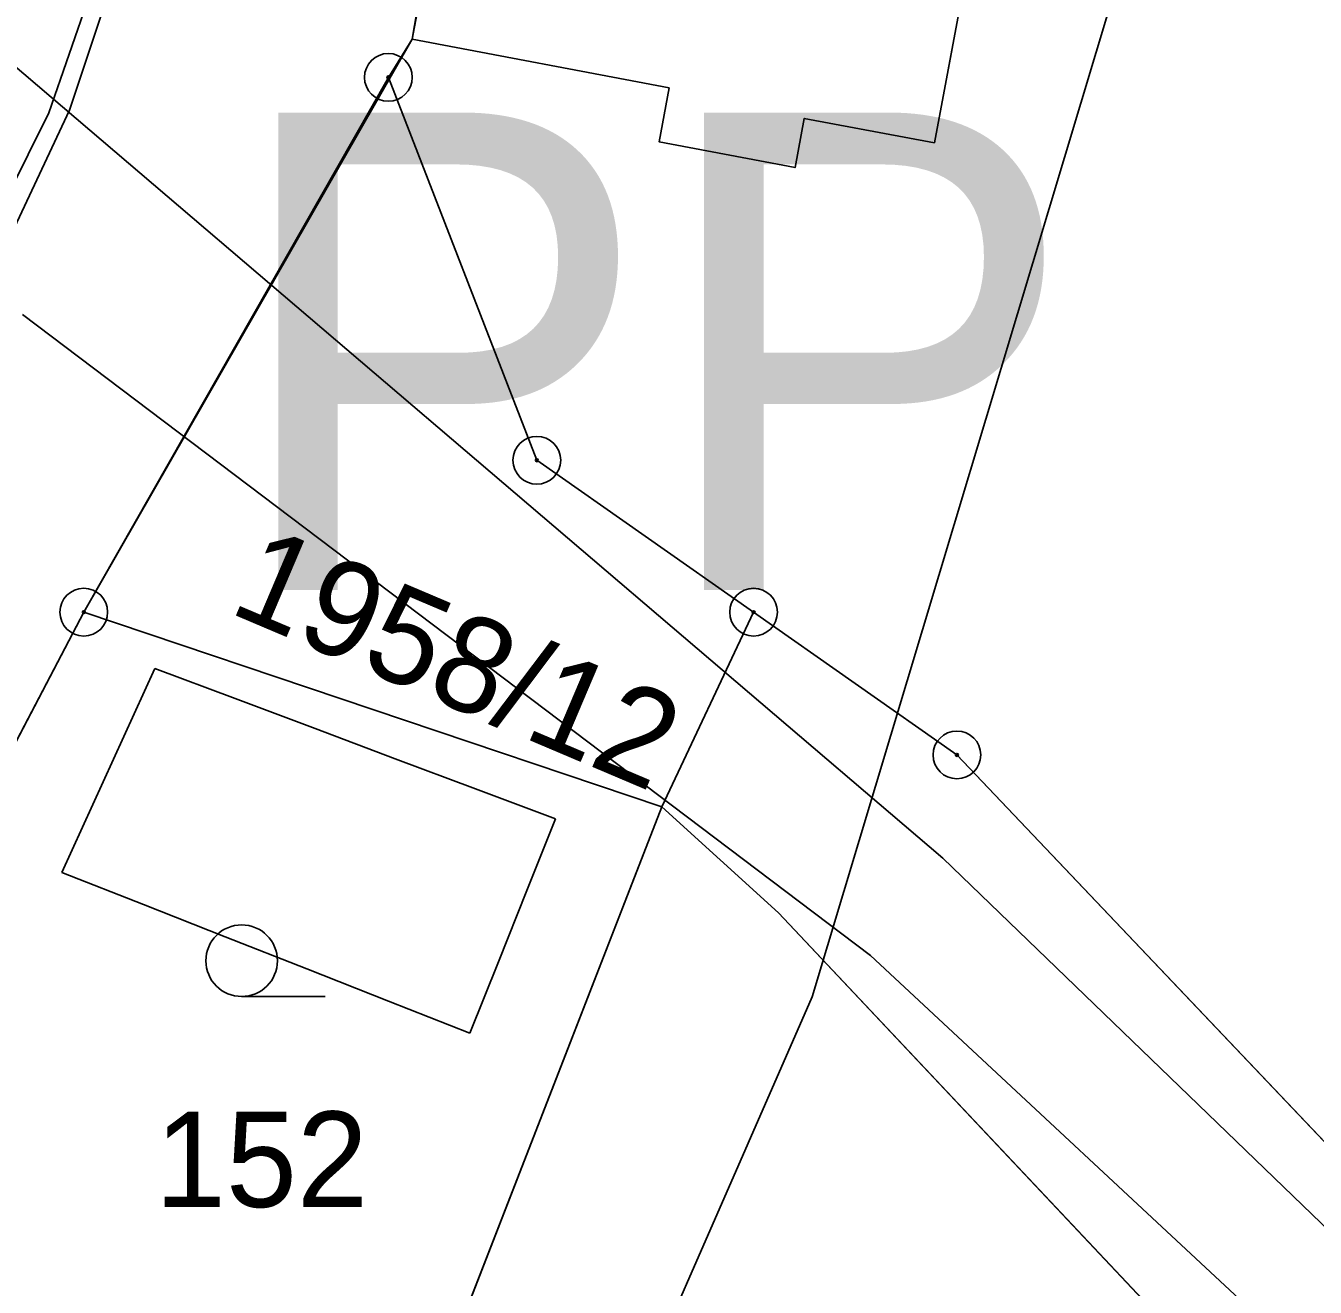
# Model space of a CAD drawing. Extents: x -706130 to -698555, y -971544 to -967260.
# Drawn here: x -704338.67 to -704311.66, y -970237.74 to -970211.32 of the extents above; entities that cross this region are included whole.
import ezdxf

# ---------------------------------------------------------------- set-up
doc = ezdxf.new("R2010")
doc.units = 0
for name, color, linetype in [('_Doplněk budov pro zastavěnost', 7, 'Continuous'), ('BPEJ I-II trida ochrany S', 7, 'Continuous'), ('Docházková izochrona - BUS S', 7, 'Continuous'), ('Docházková izochrona - VLAK N', 7, 'Continuous'), ('Hranice intravilán', 7, 'Continuous'), ('Kanalizace_stoka bez rozlišení N', 7, 'Continuous'), ('KN_Budovy', 7, 'Continuous'), ('KN_Hranice_parcel', 7, 'Continuous'), ('KN_Hranice_parcel_vnitrni_kresba', 7, 'Continuous'), ('KN_Parcelni cisla', 7, 'Continuous'), ('KN_Polygon parcely', 7, 'Continuous'), ('KN_POZEMKY_13_ZASTAVENA PLOCHA', 7, 'Continuous'), ('KN_POZEMKY_14_OSTATNI PLOCHA', 7, 'Continuous'), ('KN_POZEMKY_5_ZAHRADA', 7, 'Continuous'), ('KN_POZEMKY_7_TTP', 7, 'Continuous'), ('KN_VYUZITI_16_ostatni plocha_silnice', 7, 'Continuous'), ('KN_VYUZITI_17_ostatni plocha_ostatni komunikace', 7, 'Continuous'), ('KN_Značky bodu BP', 7, 'Continuous'), ('KN_Značky kultur', 7, 'Continuous'), ('Komunikace III třídy osy S', 7, 'Continuous'), ('Plochy doprava silniční - silnice III třídy S', 7, 'Continuous'), ('Plochy N_P ŠRAFY', 7, 'Continuous'), ('Plochy smíšené obytné venkovské N', 7, 'Continuous'), ('Plochy smíšené obytné venkovské S', 7, 'Continuous'), ('Plochy verejnych prostranstvi - komunikace ostatni S', 7, 'Continuous'), ('Plochy vodní a vodních toku_linie zatrubněný tok S', 7, 'Continuous'), ('Plochy zmen_ zastavitelne plochy', 7, 'Continuous'), ('Plochy zmen_ zastavitelne plochy_ZAKL', 7, 'Continuous'), ('Plynovody STL N', 7, 'Continuous'), ('Regulační bloky zastavitelné N', 7, 'Continuous'), ('Regulační bloky zastavěné S', 7, 'Continuous'), ('Regulační kódy zastavěné S', 7, 'Continuous'), ('Trasy cykloturistické N', 7, 'Continuous'), ('Zastavene uzemi N', 7, 'Continuous'), ('Zastavene uzemi plochy N', 7, 'Continuous'), ('Zábory hodnocené - plochy', 7, 'Continuous'), ('Zábory hodnocené - prevzate z UPO I a II tridy ochrany ZPF', 7, 'Continuous')]:
    doc.layers.add(name, color=color, linetype=linetype)

msp = doc.modelspace()

# ---------------------------------------------------------------- linework, layer by layer
at = {"layer": '_Doplněk budov pro zastavěnost'}
for p, q in [((-704336.61, -970226.203), (-704335.96, -970224.78)), ((-704335.96, -970224.78), (-704334.282, -970225.41)), ((-704334.282, -970225.41), (-704332.604, -970226.04)), ((-704332.604, -970226.04), (-704330.926, -970226.67)), ((-704337.26, -970227.627), (-704336.61, -970226.203)), ((-704330.926, -970226.67), (-704329.248, -970227.3)), ((-704329.248, -970227.3), (-704327.57, -970227.93)), ((-704337.91, -970229.05), (-704337.26, -970227.627)), ((-704327.57, -970227.93), (-704328.167, -970229.427)), ((-704336.2, -970229.724), (-704337.91, -970229.05)), ((-704328.167, -970229.427), (-704328.763, -970230.923)), ((-704334.49, -970230.398), (-704336.2, -970229.724)), ((-704332.78, -970231.072), (-704334.49, -970230.398)), ((-704328.763, -970230.923), (-704329.36, -970232.42)), ((-704331.07, -970231.746), (-704332.78, -970231.072)), ((-704329.36, -970232.42), (-704331.07, -970231.746))]:
    msp.add_line(p, q, dxfattribs=at)
at = {"layer": 'BPEJ I-II trida ochrany S'}
for p, q in [((-704337.45, -970223.6), (-704350.46, -970248.43)), ((-704325.34, -970227.68), (-704337.45, -970223.6)), ((-704322.9, -970229.9), (-704325.34, -970227.68)), ((-704300.46, -970253.7), (-704322.9, -970229.9))]:
    msp.add_line(p, q, dxfattribs=at)
at = {"layer": 'Docházková izochrona - BUS S'}
msp.add_arc((-704361.829, -969946.93), 400, 155.51821, 17.33949, dxfattribs=at)
at = {"layer": 'Docházková izochrona - VLAK N'}
msp.add_circle((-704165.451, -969778.767), 800, dxfattribs=at)
at = {"layer": 'Hranice intravilán'}
msp.add_lwpolyline([(-704236.96, -970276.21), (-704246.98, -970274.18), (-704251.4, -970273.29), (-704285.92, -970266.3), (-704300.46, -970253.7), (-704322.9, -970229.9), (-704325.34, -970227.68), (-704336.11, -970255.37), (-704346.87, -970276.54), (-704326.71, -970292.84)], dxfattribs=at)
at = {"layer": 'Kanalizace_stoka bez rozlišení N'}
for points in [[(-704315.708, -970108.899), (-704316.113, -970109.917), (-704324.867, -970134.026), (-704326.632, -970179.784), (-704337.75, -970213.085), (-704365.425, -970272.107), (-704371.374, -970294.506), (-704373.709, -970351.804), (-704376.113, -970385.719), (-704398.194, -970423.758)], [(-704338.733, -970217.369), (-704320.973, -970230.788), (-704296.056, -970253.992)]]:
    msp.add_lwpolyline(points, dxfattribs=at)
at = {"layer": 'KN_Budovy'}
msp.add_lwpolyline([(-704330.57, -970211.6), (-704325.19, -970212.62), (-704325.4, -970213.75), (-704322.55, -970214.29), (-704322.36, -970213.26), (-704319.63, -970213.77), (-704317.74, -970203.66), (-704328.65, -970201.47)], close=True, dxfattribs=at)
at = {"layer": 'KN_Hranice_parcel'}
for p, q in [((-704331.07, -970212.4), (-704337.45, -970223.6)), ((-704337.45, -970223.6), (-704350.46, -970248.43)), ((-704325.34, -970227.68), (-704337.45, -970223.6)), ((-704325.34, -970227.68), (-704323.42, -970223.6)), ((-704336.11, -970255.37), (-704325.34, -970227.68))]:
    msp.add_line(p, q, dxfattribs=at)
for points in [[(-704328.2, -970197.68), (-704328.65, -970201.47), (-704330.57, -970211.6), (-704331.07, -970212.4)], [(-704331.07, -970212.4), (-704327.96, -970220.42), (-704323.42, -970223.6)], [(-704323.42, -970223.6), (-704319.16, -970226.59), (-704310.29, -970235.93)], [(-704285.92, -970266.3), (-704300.46, -970253.7), (-704322.9, -970229.9), (-704325.34, -970227.68)]]:
    msp.add_lwpolyline(points, dxfattribs=at)
at = {"layer": 'KN_Hranice_parcel_vnitrni_kresba'}
for p, q in [((-704317.74, -970203.66), (-704319.63, -970213.77)), ((-704325.19, -970212.62), (-704330.57, -970211.6)), ((-704325.4, -970213.75), (-704325.19, -970212.62)), ((-704322.36, -970213.26), (-704322.55, -970214.29)), ((-704322.36, -970213.26), (-704319.63, -970213.77)), ((-704322.55, -970214.29), (-704325.4, -970213.75))]:
    msp.add_line(p, q, dxfattribs=at)
at = {"layer": 'KN_Polygon parcely'}
msp.add_lwpolyline([(-704366.65, -970284.79), (-704361.08, -970269.38), (-704350.46, -970248.43), (-704337.45, -970223.6), (-704331.07, -970212.4), (-704330.57, -970211.6), (-704328.65, -970201.47), (-704328.2, -970197.68), (-704327.21, -970194.48), (-704325.58, -970189.23)], dxfattribs=at)
for points in [[(-704330.57, -970211.6), (-704331.07, -970212.4), (-704327.96, -970220.42), (-704323.42, -970223.6), (-704319.16, -970226.59), (-704310.29, -970235.93), (-704306.81, -970220.57), (-704303.37, -970205.4), (-704328.2, -970197.68), (-704328.65, -970201.47)], [(-704325.34, -970227.68), (-704323.42, -970223.6), (-704327.96, -970220.42), (-704331.07, -970212.4), (-704337.45, -970223.6)], [(-704348.38, -970249.44), (-704336.11, -970255.37), (-704325.34, -970227.68), (-704337.45, -970223.6), (-704350.46, -970248.43)], [(-704244.89, -970266.42), (-704259.77, -970263.46), (-704260.88, -970266.75), (-704271.05, -970261.53), (-704272.58, -970261.48), (-704284.35, -970261.07), (-704290.77, -970255.89), (-704294.48, -970248.59), (-704302.85, -970243.53), (-704310.29, -970235.93), (-704319.16, -970226.59), (-704323.42, -970223.6), (-704325.34, -970227.68), (-704322.9, -970229.9), (-704300.46, -970253.7), (-704285.92, -970266.3), (-704251.4, -970273.29), (-704246.98, -970274.18)], [(-704266.41, -970278.02), (-704277.06, -970272.43), (-704285.92, -970266.3), (-704300.46, -970253.7), (-704322.9, -970229.9), (-704325.34, -970227.68), (-704336.11, -970255.37), (-704346.87, -970276.54), (-704326.71, -970292.84), (-704284.63, -970309.07), (-704263.93, -970315.92)]]:
    msp.add_lwpolyline(points, close=True, dxfattribs=at)
at = {"layer": 'KN_POZEMKY_13_ZASTAVENA PLOCHA'}
for p, q in [((-704330.57, -970211.6), (-704328.65, -970201.47)), ((-704331.07, -970212.4), (-704330.57, -970211.6)), ((-704327.96, -970220.42), (-704331.07, -970212.4)), ((-704323.42, -970223.6), (-704327.96, -970220.42)), ((-704319.16, -970226.59), (-704323.42, -970223.6)), ((-704310.29, -970235.93), (-704319.16, -970226.59))]:
    msp.add_line(p, q, dxfattribs=at)
at = {"layer": 'KN_POZEMKY_14_OSTATNI PLOCHA'}
for p, q in [((-704328.65, -970201.47), (-704330.57, -970211.6)), ((-704330.57, -970211.6), (-704331.07, -970212.4)), ((-704331.07, -970212.4), (-704337.45, -970223.6)), ((-704337.45, -970223.6), (-704331.07, -970212.4)), ((-704331.07, -970212.4), (-704327.96, -970220.42)), ((-704327.96, -970220.42), (-704323.42, -970223.6)), ((-704337.45, -970223.6), (-704350.46, -970248.43)), ((-704325.34, -970227.68), (-704337.45, -970223.6)), ((-704325.34, -970227.68), (-704323.42, -970223.6)), ((-704323.42, -970223.6), (-704325.34, -970227.68)), ((-704323.42, -970223.6), (-704319.16, -970226.59)), ((-704319.16, -970226.59), (-704310.29, -970235.93)), ((-704322.9, -970229.9), (-704325.34, -970227.68)), ((-704300.46, -970253.7), (-704322.9, -970229.9))]:
    msp.add_line(p, q, dxfattribs=at)
at = {"layer": 'KN_POZEMKY_5_ZAHRADA'}
for p, q in [((-704350.46, -970248.43), (-704337.45, -970223.6)), ((-704337.45, -970223.6), (-704325.34, -970227.68)), ((-704325.34, -970227.68), (-704336.11, -970255.37))]:
    msp.add_line(p, q, dxfattribs=at)
at = {"layer": 'KN_POZEMKY_7_TTP'}
for p, q in [((-704336.11, -970255.37), (-704325.34, -970227.68)), ((-704325.34, -970227.68), (-704322.9, -970229.9)), ((-704322.9, -970229.9), (-704300.46, -970253.7))]:
    msp.add_line(p, q, dxfattribs=at)
at = {"layer": 'KN_VYUZITI_16_ostatni plocha_silnice'}
for p, q in [((-704328.65, -970201.47), (-704330.57, -970211.6)), ((-704330.57, -970211.6), (-704331.07, -970212.4)), ((-704331.07, -970212.4), (-704337.45, -970223.6)), ((-704337.45, -970223.6), (-704350.46, -970248.43))]:
    msp.add_line(p, q, dxfattribs=at)
at = {"layer": 'KN_VYUZITI_17_ostatni plocha_ostatni komunikace'}
for p, q in [((-704337.45, -970223.6), (-704331.07, -970212.4)), ((-704331.07, -970212.4), (-704327.96, -970220.42)), ((-704327.96, -970220.42), (-704323.42, -970223.6)), ((-704325.34, -970227.68), (-704337.45, -970223.6)), ((-704325.34, -970227.68), (-704323.42, -970223.6)), ((-704323.42, -970223.6), (-704325.34, -970227.68)), ((-704323.42, -970223.6), (-704319.16, -970226.59)), ((-704319.16, -970226.59), (-704310.29, -970235.93)), ((-704322.9, -970229.9), (-704325.34, -970227.68)), ((-704300.46, -970253.7), (-704322.9, -970229.9))]:
    msp.add_line(p, q, dxfattribs=at)
at = {"layer": 'KN_Značky bodu BP'}
for centre, radius in [((-704331.07, -970212.4), 0.5), ((-704331.07, -970212.4), 0.0303), ((-704327.96, -970220.42), 0.5), ((-704327.96, -970220.42), 0.0303), ((-704337.45, -970223.6), 0.5), ((-704323.42, -970223.6), 0.5), ((-704337.45, -970223.6), 0.0303), ((-704323.42, -970223.6), 0.0303), ((-704319.16, -970226.59), 0.5), ((-704319.16, -970226.59), 0.0303)]:
    msp.add_circle(centre, radius, dxfattribs=at)
at = {"layer": 'KN_Značky kultur'}
msp.add_line((-704334.143, -970231.65), (-704332.393, -970231.65), dxfattribs=at)
msp.add_circle((-704334.143, -970230.9), 0.75, dxfattribs=at)
at = {"layer": 'Komunikace III třídy osy S'}
msp.add_lwpolyline([(-704330.93, -970188.51), (-704335.437, -970204.681), (-704336.48, -970208.22), (-704338.18, -970213.14), (-704340.791, -970218.395), (-704362.238, -970261.156), (-704368.668, -970276.027), (-704371.631, -970286.925), (-704374.154, -970304.881), (-704375.815, -970349.829), (-704377.52, -970379.09), (-704378.33, -970382.9), (-704379.81, -970387.16), (-704381.8, -970391.97), (-704383.72, -970396.25), (-704386.32, -970401.18), (-704392.36, -970410.73), (-704399.98, -970422.96)], dxfattribs=at)
at = {"layer": 'Plochy doprava silniční - silnice III třídy S'}
for p, q in [((-704330.57, -970211.6), (-704328.65, -970201.47)), ((-704331.07, -970212.4), (-704330.57, -970211.6)), ((-704337.45, -970223.6), (-704331.07, -970212.4)), ((-704350.46, -970248.43), (-704337.45, -970223.6))]:
    msp.add_line(p, q, dxfattribs=at)
at = {"layer": 'Plochy N_P ŠRAFY'}
for p, q in [((-704323.42, -970223.6), (-704325.34, -970227.68)), ((-704325.34, -970227.68), (-704336.11, -970255.37))]:
    msp.add_line(p, q, dxfattribs=at)
msp.add_lwpolyline([(-704310.29, -970235.93), (-704319.16, -970226.59), (-704323.42, -970223.6)], dxfattribs=at)
at = {"layer": 'Plochy smíšené obytné venkovské N'}
for p, q in [((-704323.42, -970223.6), (-704325.34, -970227.68)), ((-704325.34, -970227.68), (-704336.11, -970255.37))]:
    msp.add_line(p, q, dxfattribs=at)
msp.add_lwpolyline([(-704310.29, -970235.93), (-704319.16, -970226.59), (-704323.42, -970223.6)], dxfattribs=at)
at = {"layer": 'Plochy smíšené obytné venkovské S'}
for p, q in [((-704328.65, -970201.47), (-704330.57, -970211.6)), ((-704330.57, -970211.6), (-704331.07, -970212.4)), ((-704337.45, -970223.6), (-704350.46, -970248.43)), ((-704325.34, -970227.68), (-704337.45, -970223.6)), ((-704336.11, -970255.37), (-704325.34, -970227.68))]:
    msp.add_line(p, q, dxfattribs=at)
for points in [[(-704331.07, -970212.4), (-704327.96, -970220.42), (-704323.42, -970223.6)], [(-704323.42, -970223.6), (-704319.16, -970226.59), (-704310.29, -970235.93)]]:
    msp.add_lwpolyline(points, dxfattribs=at)
at = {"layer": 'Plochy verejnych prostranstvi - komunikace ostatni S'}
for p, q in [((-704331.07, -970212.4), (-704337.45, -970223.6)), ((-704327.96, -970220.42), (-704331.07, -970212.4)), ((-704323.42, -970223.6), (-704327.96, -970220.42)), ((-704337.45, -970223.6), (-704325.34, -970227.68)), ((-704325.34, -970227.68), (-704323.42, -970223.6))]:
    msp.add_line(p, q, dxfattribs=at)
at = {"layer": 'Plochy vodní a vodních toku_linie zatrubněný tok S'}
for points in [[(-704322.195, -970231.658), (-704315.577, -970209.662), (-704310.452, -970190.609), (-704310.025, -970177.978), (-704308.103, -970157.425), (-704307.462, -970138.586), (-704307.462, -970124.666), (-704314.585, -970112.421), (-704319.309, -970105.942)], [(-704351.63, -970286.842), (-704343.453, -970280.248), (-704322.195, -970231.658)]]:
    msp.add_lwpolyline(points, dxfattribs=at)
at = {"layer": 'Plochy zmen_ zastavitelne plochy'}
msp.add_lwpolyline([(-704351.62, -970285.42), (-704346.87, -970276.54), (-704336.11, -970255.37), (-704325.34, -970227.68), (-704323.42, -970223.6), (-704319.16, -970226.59), (-704310.29, -970235.93), (-704302.85, -970243.53), (-704294.48, -970248.59), (-704286.71, -970225.41), (-704281.8, -970209.65), (-704275.41, -970210.91), (-704251.29, -970214.31), (-704249.33, -970214.59), (-704249.17, -970213.48), (-704247.74, -970203.29), (-704230.21, -970196.19)], dxfattribs=at)
at = {"layer": 'Plochy zmen_ zastavitelne plochy_ZAKL'}
for p, q in [((-704323.42, -970223.6), (-704325.34, -970227.68)), ((-704325.34, -970227.68), (-704336.11, -970255.37))]:
    msp.add_line(p, q, dxfattribs=at)
msp.add_lwpolyline([(-704310.29, -970235.93), (-704319.16, -970226.59), (-704323.42, -970223.6)], dxfattribs=at)
at = {"layer": 'Plynovody STL N'}
msp.add_lwpolyline([(-704341.145, -970210.248), (-704319.452, -970228.75), (-704295.073, -970252.27)], dxfattribs=at)
at = {"layer": 'Regulační bloky zastavitelné N'}
for p, q in [((-704323.42, -970223.6), (-704325.34, -970227.68)), ((-704325.34, -970227.68), (-704336.11, -970255.37))]:
    msp.add_line(p, q, dxfattribs=at)
msp.add_lwpolyline([(-704310.29, -970235.93), (-704319.16, -970226.59), (-704323.42, -970223.6)], dxfattribs=at)
at = {"layer": 'Regulační bloky zastavěné S'}
for p, q in [((-704330.57, -970211.6), (-704328.65, -970201.47)), ((-704328.65, -970201.47), (-704330.57, -970211.6)), ((-704331.07, -970212.4), (-704330.57, -970211.6)), ((-704330.57, -970211.6), (-704331.07, -970212.4)), ((-704337.45, -970223.6), (-704331.07, -970212.4)), ((-704331.07, -970212.4), (-704337.45, -970223.6)), ((-704327.96, -970220.42), (-704331.07, -970212.4)), ((-704323.42, -970223.6), (-704327.96, -970220.42)), ((-704337.45, -970223.6), (-704350.46, -970248.43)), ((-704350.46, -970248.43), (-704337.45, -970223.6)), ((-704325.34, -970227.68), (-704337.45, -970223.6)), ((-704337.45, -970223.6), (-704325.34, -970227.68)), ((-704325.34, -970227.68), (-704323.42, -970223.6)), ((-704336.11, -970255.37), (-704325.34, -970227.68))]:
    msp.add_line(p, q, dxfattribs=at)
for points in [[(-704331.07, -970212.4), (-704327.96, -970220.42), (-704323.42, -970223.6)], [(-704323.42, -970223.6), (-704319.16, -970226.59), (-704310.29, -970235.93)]]:
    msp.add_lwpolyline(points, dxfattribs=at)
at = {"layer": 'Trasy cykloturistické N'}
msp.add_lwpolyline([(-704397.28, -970427.29), (-704386.46, -970409.76), (-704381.94, -970403.15), (-704375.12, -970393.19), (-704372.65, -970386.41), (-704370.59, -970346.53), (-704369.52, -970316.88), (-704368.75, -970300.09), (-704366.65, -970284.79), (-704361.08, -970269.38), (-704350.46, -970248.43), (-704337.45, -970223.6), (-704330.57, -970211.6), (-704328.2, -970197.68), (-704324.27, -970184.8)], dxfattribs=at)
at = {"layer": 'Zastavene uzemi N'}
msp.add_lwpolyline([(-704326.71, -970292.84), (-704346.87, -970276.54), (-704336.11, -970255.37), (-704325.34, -970227.68), (-704322.9, -970229.9), (-704300.46, -970253.7), (-704285.92, -970266.3), (-704251.4, -970273.29), (-704246.98, -970274.18), (-704236.96, -970276.21)], dxfattribs=at)
at = {"layer": 'Zastavene uzemi plochy N'}
msp.add_lwpolyline([(-704326.71, -970292.84), (-704346.87, -970276.54), (-704336.11, -970255.37), (-704325.34, -970227.68), (-704322.9, -970229.9), (-704300.46, -970253.7), (-704285.92, -970266.3), (-704251.4, -970273.29), (-704246.98, -970274.18), (-704236.96, -970276.21)], dxfattribs=at)
at = {"layer": 'Zábory hodnocené - plochy'}
for p, q in [((-704323.42, -970223.6), (-704325.34, -970227.68)), ((-704325.34, -970227.68), (-704336.11, -970255.37))]:
    msp.add_line(p, q, dxfattribs=at)
msp.add_lwpolyline([(-704310.29, -970235.93), (-704319.16, -970226.59), (-704323.42, -970223.6)], dxfattribs=at)
at = {"layer": 'Zábory hodnocené - prevzate z UPO I a II tridy ochrany ZPF'}
for p, q in [((-704323.42, -970223.6), (-704325.34, -970227.68)), ((-704325.34, -970227.68), (-704336.11, -970255.37))]:
    msp.add_line(p, q, dxfattribs=at)
msp.add_lwpolyline([(-704310.29, -970235.93), (-704319.16, -970226.59), (-704323.42, -970223.6)], dxfattribs=at)

# ---------------------------------------------------------------- texts
at = {"layer": 'KN_Parcelni cisla'}
msp.add_text('1958/12', height=2, rotation=337, dxfattribs=at).set_placement((-704334.452, -970223.592))
msp.add_text('152', height=2, dxfattribs=at).set_placement((-704335.96, -970236.059))
at = {"layer": 'Regulační kódy zastavěné S'}
msp.add_text('PP', height=10, dxfattribs=at).set_placement((-704334.474, -970223.137))

doc.saveas('drawing.dxf')
